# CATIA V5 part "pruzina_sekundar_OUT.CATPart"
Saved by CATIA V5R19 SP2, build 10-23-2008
Part number: Pruzina_sekundar_OUT
Bounding box of the stored display mesh (mm): x -173.999 to 174, y -173.998 to 173.997, z 50 to 380
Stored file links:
  C:\Users\Martiin\Desktop\9.semestr\Projekt-diplomka\3D model\pruzina_sekundar_OUT.CATPart
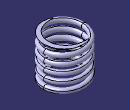
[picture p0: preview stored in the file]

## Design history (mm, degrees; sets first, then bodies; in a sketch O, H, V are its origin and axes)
Body1 (main body)
  Line1: type PtDir, RefPoint {point type Coord, X 0, Y 0, Z 0}, Direction xy-plane, Support zx-plane, Start 0, End 176
  Point1: type OnPlane, Support xy-plane, H 155, V 0, Direction (1, 0, 0)
  Helix1: Direction Line1, RefPoint Point1, Pitch 63.3333, Height 506.664, TaperAngle 0
  Plane1: type Normal, Curve Helix1, RefPoint Point1
  Sketch1 on Plane1, origin (0, 0, 0), H (-1, 0, 0), V (0, -0.0649, 0.9979)
    circle A1 centre (-155, 0) radius 19
    point P1 (-155, 0)
    reference projected point E1 (-155, 0) from Point1
    radius A1 = 19
    coincidence: E1 P1
  Rib1: profile Sketch1, centre curve Helix1
  Plane2: type Offset, RefPlane xy-plane, Offset 50
  Split1: SplitPlane Plane2
  Plane3: type Offset, RefPlane xy-plane, Offset 380
  Split2: SplitPlane Plane3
